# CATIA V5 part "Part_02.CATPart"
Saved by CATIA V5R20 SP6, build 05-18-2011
Part number: Part_02
Bounding box of the stored display mesh (mm): x -7.5 to 7.5, y 0 to 30, z 0 to 18
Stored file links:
  E:\#01 CATIA Lecture Materials\#16 3D Print Test\3D Print Test\14th Test\Part_02.CATPart
  E:\#01 CATIA Lecture Materials\#16 3D Print Test\3D Print Test\2nd Test\3D Print Test_02.CATProduct
  E:\#01 CATIA Lecture Materials\#16 3D Print Test\3D Print Test\14th Test\Part_01.CATPart
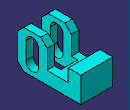
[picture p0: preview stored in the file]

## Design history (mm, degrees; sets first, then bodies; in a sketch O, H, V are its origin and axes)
Set1 "Reference Data"
  Point1 "Center Point": (0, 0, 0)
Body1 (main body)
Body2
  Sketch1 on yz-plane, origin (0, 0, 0), H (0, -1, 0), V (0, 0, 1)
    line L1 (0, 0) -> (0, 18)
    line L2 (0, 18) -> (-14, 18)
    line L3 (-14, 18) -> (-14, 6)
    line L4 (-14, 6) -> (-24, 6)
    line L5 (-24, 6) -> (-24, 12)
    line L6 (-24, 12) -> (-30, 12)
    line L7 (-30, 12) -> (-30, 0)
    point P7 (-30, 0)
    line L8 (-30, 0) -> (0, 0)
    distance L1 L3 = 14
    distance L3 L5 = 10
    distance L4 L8 = 6
    distance L6 L8 = 12
    distance L7 L1 = 30
    distance L8 L2 = 18
    vertical: L1 V, L3 V, L5 V, L7 V
    horizontal: L2 H, L4 H, L6 H, L8 H
    coincidence: P7 H
  Pad1: profile Sketch1, direction (-1, 0, 0), length 7.5, mirrored extent
  Sketch2 on yz-plane, origin (0, 0, 0), H (0, -1, 0), V (0, 0, 1)
    construction line L1 (-7, 13) -> (-7, 5)
    point P1 (-7, 13)
    point P2 (-7, 5)
    line L2 (-4, 13) -> (-4, 5)
    line L3 (-10, 5) -> (-10, 13)
    arc A1 centre (-7, 5) radius 3 from (-4, 5) to (-10, 5) cw
    arc A2 centre (-7, 13) radius 3 from (-10, 13) to (-4, 13) cw
    distance V L1 = 7
    distance H P2 = 5
    distance P2 P1 = 8
    radius A2 = 3
    vertical: L1 V, L2 V
    tangency: A1 L2, A2 L2, A1 L3, A2 L3
  Pocket1: profile Sketch2, direction (1, 0, 0), through (limit type 6), opposite side through (limit type 6)
  Chamfer1: length 3, angle 45, on edge [face of Pad1 from Sketch1.L3 | face of Pad1 from Sketch1.L2]; edge [face of Pad1 from Sketch1.L2 | face of Pad1 from Sketch1.L1]; edge [face of Pad1 from Sketch1.L1 | face of Pad1 from Sketch1.L8]
  Sketch3 on xy-plane, origin (0, 0, 0), H (0, -1, 0), V (1, 0, 0)
    line L1 (-17, 4) -> (0, 4)
    line L2 (0, 4) -> (0, -4)
    line L3 (0, -4) -> (-17, -4)
    line L4 (-17, -4) -> (-17, 4)
    point P3 (0, -4)
    distance L1 L3 = 8
    distance V L4 = 17
    horizontal: L1 H, L3 H
    vertical: L2 V, L4 V
    coincidence: P3 V
    symmetry: L1 L3 H
  Pocket2: profile Sketch3, direction (0, 0, -1), through (limit type 6)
